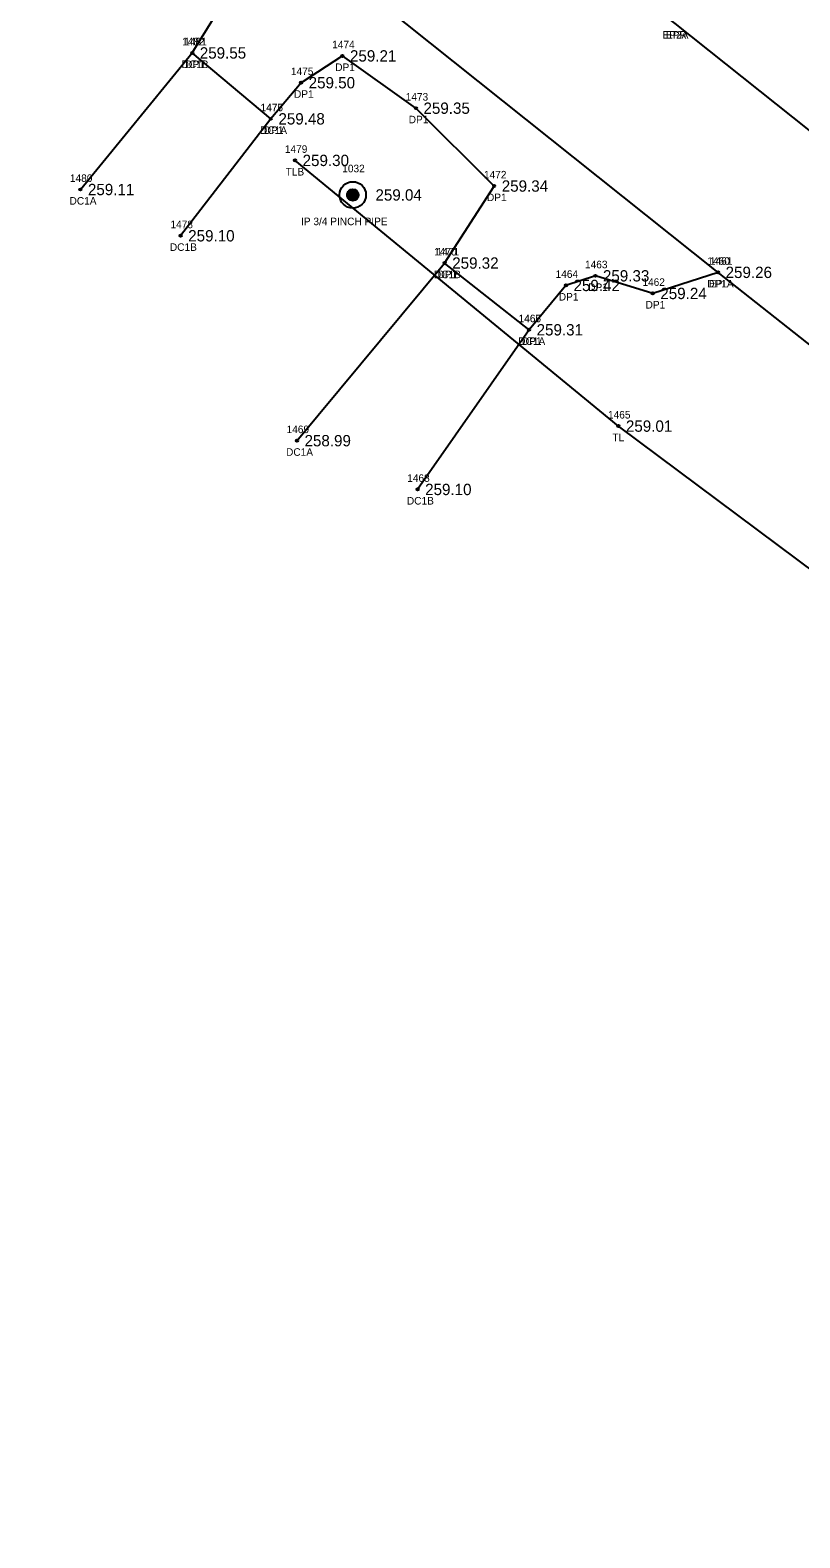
# Model space of a CAD drawing. Extents: x 1961231 to 1962574, y 799865 to 801120.
# Drawn here: x 1961710.5 to 1961812.2, y 800515.1 to 800714.6 of the extents above; entities that cross this region are included whole.
import ezdxf

# ---------------------------------------------------------------- set-up
doc = ezdxf.new("R2010")
doc.units = 0
for name, color, linetype in [('RD_EX_Conc', 7, 'Continuous'), ('RD_EX_Conc_txCode', 7, 'Continuous'), ('RD_EX_Driveway', 7, 'Continuous'), ('RD_EX_Driveway_txCode', 7, 'Continuous'), ('RD_EX_DV_Prop_txCode', 7, 'Continuous'), ('RD_EX_DV_PropPin', 7, 'Continuous'), ('RD_EX_Road', 7, 'Continuous'), ('RD_EX_Road_txCode', 7, 'Continuous'), ('RD_EX_TX_Conc_ELEV', 7, 'Continuous'), ('RD_EX_TX_Driveway_ELEV', 7, 'Continuous'), ('RD_EX_TX_DV_Prop_ELEV', 7, 'Continuous'), ('RD_EX_TX_Road_ELEV', 7, 'Continuous'), ('RD_EX_TX_VEG_ELEV', 7, 'Continuous'), ('RD_EX_VEG', 7, 'Continuous'), ('RD_EX_VEG_txCode', 7, 'Continuous'), ('RD_SMD_Locator', 7, 'Continuous')]:
    doc.layers.add(name, color=color, linetype=linetype)

msp = doc.modelspace()

# ---------------------------------------------------------------- linework, layer by layer
at = {"layer": 'RD_EX_Conc'}
for p, q in [((1961717.1, 800693.53), (1961731.89, 800711.6)), ((1961742.29, 800702.88), (1961730.36, 800687.41)), ((1961745.74, 800660.3), (1961765.27, 800683.8)), ((1961776.43, 800674.97), (1961761.69, 800653.85))]:
    msp.add_line(p, q, dxfattribs=at)
at = {"layer": 'RD_EX_Driveway'}
msp.add_lwpolyline([(1961801.42, 800682.57), (1961792.79, 800679.78), (1961785.2, 800682.11), (1961781.31, 800680.84), (1961776.43, 800674.97), (1961765.27, 800683.8), (1961771.82, 800693.99), (1961761.47, 800704.29), (1961751.75, 800711.21), (1961746.29, 800707.66), (1961742.29, 800702.88), (1961731.89, 800711.6), (1961735.94, 800718.16), (1961732.79, 800728.82), (1961728.41, 800740.86)], dxfattribs=at)
at = {"layer": 'RD_EX_DV_PropPin'}
for p, q in [((1961752.42, 800692.51), (1961752.42, 800693.11)), ((1961752.45, 800692.44), (1961752.45, 800693.18)), ((1961752.49, 800692.39), (1961752.49, 800693.24)), ((1961752.52, 800692.34), (1961752.52, 800693.29)), ((1961752.56, 800692.3), (1961752.56, 800693.33)), ((1961752.59, 800692.26), (1961752.59, 800693.36)), ((1961752.63, 800692.23), (1961752.63, 800693.39)), ((1961752.66, 800692.2), (1961752.66, 800693.42)), ((1961752.7, 800692.18), (1961752.7, 800693.45)), ((1961752.73, 800692.16), (1961752.73, 800693.47)), ((1961752.77, 800692.14), (1961752.77, 800693.49)), ((1961752.8, 800692.12), (1961752.8, 800693.51)), ((1961752.84, 800692.1), (1961752.84, 800693.52)), ((1961752.87, 800692.09), (1961752.87, 800693.53)), ((1961752.91, 800692.08), (1961752.91, 800693.54)), ((1961752.94, 800692.07), (1961752.94, 800693.55)), ((1961752.98, 800692.06), (1961752.98, 800693.56)), ((1961753.01, 800692.06), (1961753.01, 800693.57)), ((1961753.05, 800692.05), (1961753.05, 800693.57)), ((1961753.08, 800692.05), (1961753.08, 800693.57)), ((1961753.12, 800692.05), (1961753.12, 800693.57)), ((1961753.15, 800692.05), (1961753.15, 800693.57)), ((1961753.19, 800692.05), (1961753.19, 800693.57)), ((1961753.22, 800692.06), (1961753.22, 800693.57)), ((1961753.26, 800692.06), (1961753.26, 800693.56)), ((1961753.29, 800692.07), (1961753.29, 800693.55)), ((1961753.33, 800692.08), (1961753.33, 800693.54)), ((1961753.36, 800692.09), (1961753.36, 800693.53)), ((1961753.4, 800692.1), (1961753.4, 800693.52)), ((1961753.43, 800692.12), (1961753.43, 800693.51)), ((1961753.47, 800692.14), (1961753.47, 800693.49)), ((1961753.5, 800692.16), (1961753.5, 800693.47)), ((1961753.54, 800692.18), (1961753.54, 800693.45)), ((1961753.57, 800692.2), (1961753.57, 800693.42)), ((1961753.61, 800692.23), (1961753.61, 800693.39)), ((1961753.64, 800692.26), (1961753.64, 800693.36)), ((1961753.68, 800692.3), (1961753.68, 800693.33)), ((1961753.71, 800692.34), (1961753.71, 800693.29)), ((1961753.75, 800692.39), (1961753.75, 800693.24)), ((1961753.78, 800692.44), (1961753.78, 800693.18)), ((1961753.82, 800692.51), (1961753.82, 800693.11)), ((1961752.38, 800692.62), (1961752.38, 800693.01)), ((1961753.85, 800692.62), (1961753.85, 800693.01))]:
    msp.add_line(p, q, dxfattribs=at)
for radius in [1.75, 0.761]:
    msp.add_circle((1961753.12, 800692.81), radius, dxfattribs=at)
at = {"layer": 'RD_EX_Road'}
for points in [[(1962276.74, 800366.53), (1962275.76, 800367.28), (1962226.46, 800400.66), (1962183.05, 800429.73), (1962145.98, 800455.38), (1962104.4, 800484.06), (1962056.77, 800517.94), (1962023.95, 800541.05), (1961991.87, 800563.56), (1961983.89, 800569.94), (1961938.77, 800603.67), (1961913.43, 800623.83), (1961897.73, 800636.17), (1961851.62, 800671.61), (1961815.86, 800699.48), (1961795.77, 800715.49), (1961771.88, 800733.73), (1961750.77, 800750.96), (1961735.63, 800762.82), (1961702.92, 800788.52)], [(1962241.79, 800315.68), (1962238.35, 800317.6), (1962189.92, 800352.69), (1962151.64, 800383.49), (1962113.78, 800416.39), (1962074.11, 800451.29), (1962034.78, 800486.96), (1962017.07, 800503.17), (1961999.46, 800519.25), (1961962.48, 800552.12), (1961937.08, 800573.11), (1961923.19, 800584.9), (1961883.07, 800617.43), (1961838.29, 800653.43), (1961801.42, 800682.57), (1961728.41, 800740.86), (1961722.95, 800745.11), (1961689.13, 800771.93)]]:
    msp.add_lwpolyline(points, dxfattribs=at)
at = {"layer": 'RD_EX_VEG'}
msp.add_lwpolyline([(1961986.16, 800417.05), (1962008.73, 800486.69), (1961986.14, 800509.28), (1961949.4, 800540.42), (1961909.42, 800571.42), (1961867.44, 800598.73), (1961825.04, 800634.78), (1961788.24, 800662.23), (1961745.49, 800697.38)], dxfattribs=at)
at = {"layer": 'RD_SMD_Locator'}
for centre in [(1961731.89, 800711.6), (1961731.89, 800711.6), (1961751.75, 800711.21), (1961746.29, 800707.66), (1961742.29, 800702.88), (1961742.29, 800702.88), (1961761.47, 800704.29), (1961745.49, 800697.38), (1961717.1, 800693.53), (1961771.82, 800693.99), (1961753.12, 800692.81), (1961730.36, 800687.41), (1961765.27, 800683.8), (1961765.27, 800683.8), (1961785.2, 800682.11), (1961801.42, 800682.57), (1961801.42, 800682.57), (1961781.31, 800680.84), (1961792.79, 800679.78), (1961776.43, 800674.97), (1961776.43, 800674.97), (1961788.24, 800662.23), (1961745.74, 800660.3), (1961761.69, 800653.85)]:
    msp.add_circle(centre, 0.15, dxfattribs=at)

# ---------------------------------------------------------------- texts
at = {"layer": 'RD_EX_Conc_txCode'}
for s, p in [('1481', (1961730.83, 800712.6)), ('DC1B', (1961730.48, 800709.6)), ('1477', (1961740.94, 800703.88)), ('DC1A', (1961740.86, 800700.88)), ('1480', (1961715.72, 800694.53)), ('DC1A', (1961715.67, 800691.53)), ('1478', (1961729.01, 800688.41)), ('DC1B', (1961728.94, 800685.41)), ('1470', (1961763.88, 800684.8)), ('DC1B', (1961763.85, 800681.8)), ('1467', (1961775.06, 800675.97)), ('DC1A', (1961775, 800672.97)), ('1469', (1961744.37, 800661.3)), ('DC1A', (1961744.3, 800658.3)), ('1468', (1961760.32, 800654.85)), ('DC1B', (1961760.28, 800651.85))]:
    msp.add_text(s, height=1, dxfattribs=at).set_placement(p)
at = {"layer": 'RD_EX_Driveway_txCode'}
for s, p in [('1482', (1961730.55, 800712.6)), ('1474', (1961750.4, 800712.21)), ('DP1', (1961730.95, 800709.6)), ('1475', (1961744.94, 800708.66)), ('DP1', (1961750.8, 800709.21)), ('DP1', (1961745.35, 800705.66)), ('1473', (1961760.12, 800705.29)), ('1476', (1961740.92, 800703.88)), ('DP1', (1961760.52, 800702.29)), ('DP1', (1961741.35, 800700.88)), ('1472', (1961770.47, 800694.99)), ('DP1', (1961770.87, 800691.99)), ('1471', (1961764.21, 800684.8)), ('1463', (1961783.83, 800683.11)), ('1461', (1961800.34, 800683.57)), ('DP1', (1961764.33, 800681.8)), ('1464', (1961779.94, 800681.84)), ('DP1', (1961784.25, 800680.11)), ('1462', (1961791.42, 800680.78)), ('DP1A', (1961799.99, 800680.57)), ('DP1', (1961780.36, 800678.84)), ('DP1', (1961791.84, 800677.78)), ('1466', (1961775.04, 800675.97)), ('DP1', (1961775.49, 800672.97))]:
    msp.add_text(s, height=1, dxfattribs=at).set_placement(p)
at = {"layer": 'RD_EX_DV_Prop_txCode'}
for s, p in [('1032', (1961751.73, 800695.81)), ('IP 3/4 PINCH PIPE', (1961746.28, 800688.81))]:
    msp.add_text(s, height=1, dxfattribs=at).set_placement(p)
at = {"layer": 'RD_EX_Road_txCode'}
for s, p in [('EP2A', (1961794.08, 800713.49)), ('EPR', (1961794.54, 800713.49)), ('1460', (1961800.01, 800683.57)), ('EPL', (1961800.22, 800680.57))]:
    msp.add_text(s, height=1, dxfattribs=at).set_placement(p)
at = {"layer": 'RD_EX_TX_Conc_ELEV'}
for s, p in [('259.55', (1961732.89, 800710.85)), ('259.48', (1961743.29, 800702.13)), ('259.11', (1961718.1, 800692.78)), ('259.10', (1961731.36, 800686.66)), ('259.32', (1961766.27, 800683.05)), ('259.31', (1961777.43, 800674.22)), ('258.99', (1961746.74, 800659.55)), ('259.10', (1961762.69, 800653.1))]:
    msp.add_text(s, height=1.5, dxfattribs=at).set_placement(p)
at = {"layer": 'RD_EX_TX_Driveway_ELEV'}
for s, p in [('259.55', (1961732.89, 800710.85)), ('259.21', (1961752.75, 800710.46)), ('259.50', (1961747.29, 800706.91)), ('259.35', (1961762.47, 800703.54)), ('259.48', (1961743.29, 800702.13)), ('259.34', (1961772.82, 800693.24)), ('259.32', (1961766.27, 800683.05)), ('259.26', (1961802.42, 800681.82)), ('259.42', (1961782.31, 800680.09)), ('259.33', (1961786.2, 800681.36)), ('259.24', (1961793.79, 800679.03)), ('259.31', (1961777.43, 800674.22))]:
    msp.add_text(s, height=1.5, dxfattribs=at).set_placement(p)
at = {"layer": 'RD_EX_TX_DV_Prop_ELEV'}
msp.add_text('259.04', height=1.5, dxfattribs=at).set_placement((1961756.12, 800692.06))
at = {"layer": 'RD_EX_TX_Road_ELEV'}
msp.add_text('259.26', height=1.5, dxfattribs=at).set_placement((1961802.42, 800681.82))
at = {"layer": 'RD_EX_TX_VEG_ELEV'}
for s, p in [('259.30', (1961746.49, 800696.63)), ('259.01', (1961789.24, 800661.48))]:
    msp.add_text(s, height=1.5, dxfattribs=at).set_placement(p)
at = {"layer": 'RD_EX_VEG_txCode'}
for s, p in [('1479', (1961744.14, 800698.38)), ('TLB', (1961744.24, 800695.38)), ('1465', (1961786.87, 800663.23)), ('TL', (1961787.46, 800660.23))]:
    msp.add_text(s, height=1, dxfattribs=at).set_placement(p)

doc.saveas('drawing.dxf')
